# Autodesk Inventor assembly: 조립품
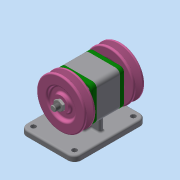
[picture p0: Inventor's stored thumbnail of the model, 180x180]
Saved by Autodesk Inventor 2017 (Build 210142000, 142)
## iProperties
Part Number: 조립품
Material: 일반
Document SubType Name: Assembly
Designer: mrc
Author: mrc
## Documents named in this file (10)
- C:\Users\mrc\Desktop\701106V1028\조립품.iam
- C:\Users\mrc\Desktop\701106V1028\V-벨트풀리.ipt
- C:\Users\mrc\Desktop\701106V1028\너트 M10x1.ipt
- C:\Users\mrc\Desktop\701106V1028\베어링 6004.ipt
- C:\Users\mrc\Desktop\701106V1028\본체.ipt
- C:\Users\mrc\Desktop\701106V1028\볼트 M4.ipt
- C:\Users\mrc\Desktop\701106V1028\오일 실 17 30 5.ipt
- C:\Users\mrc\Desktop\701106V1028\축.ipt
- C:\Users\mrc\Desktop\701106V1028\커버.ipt
- C:\Users\mrc\Desktop\701106V1028\키 5 x 5 x 12.ipt
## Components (2 placed, 1 different names)
1. V-벨트풀리:1
2. V-벨트풀리:2
